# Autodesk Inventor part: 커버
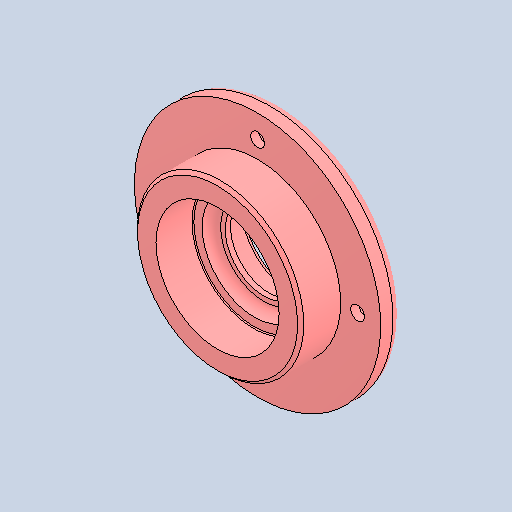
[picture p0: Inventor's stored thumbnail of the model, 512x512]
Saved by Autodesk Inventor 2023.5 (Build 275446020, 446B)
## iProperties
Created: 2026-07
Part Number: 커버
Material: 알루미늄 6061
Document SubType Name: Modeling
Designer: mirae
Density: 2.7 g/cm^3
Appearance: 기본값
Company: 한국ATC센터
Author: jhkim
Revision Number: 1
Sending System: Autodesk Inventor 2027
Preprocessor: ST-DEVELOPER v20.1
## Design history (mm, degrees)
node "커버1"
node "솔리드2"
node "솔리드1"
